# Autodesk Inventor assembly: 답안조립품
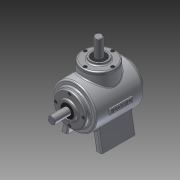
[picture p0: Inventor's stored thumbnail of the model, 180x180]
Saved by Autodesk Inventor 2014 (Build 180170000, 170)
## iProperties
Created: 2015-01
Part Number: 답안조립품
Document SubType Name: Assembly
Designer: user
Author: user
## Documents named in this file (15)
- C:\Users\user\Desktop\450106V1026\답안조립품.iam
- C:\Users\user\Desktop\450106V1026\1-본체.ipt
- C:\Users\user\Desktop\450106V1026\M4.ipt
- C:\Users\user\Desktop\450106V1026\메인 베벨기어.ipt
- C:\Users\user\Desktop\450106V1026\메인 축.ipt
- 메인 축.ipt
- C:\Users\user\Desktop\450106V1026\베어링 6203.ipt
- C:\Users\user\Desktop\450106V1026\서브 베벨기어.ipt
- C:\Users\user\Desktop\450106V1026\서브 축.ipt
- 서브 축.ipt
- C:\Users\user\Desktop\450106V1026\오일실.ipt
- C:\Users\user\Desktop\450106V1026\커버.ipt
- C:\Users\user\Desktop\450106V1026\커버2.ipt
- C:\Users\user\Desktop\450106V1026\키 4x4.ipt
- C:\Users\user\Desktop\450106V1026\키 5x5.ipt
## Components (13 placed, 2 different names)
1. 1-본체:1 — Insert:1, Insert:2, Insert:3, Insert:4, Insert:11, Insert:12
2. M4:9
3. M4:10
4. M4:11
5. M4:12
6. M4:2 — Insert:18
7. M4:3
8. M4:4
9. M4:5
10. M4:1 — Insert:19
11. M4:6
12. M4:7
13. M4:8
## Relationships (8: Insert 8)
- Insert:1: 1-본체:1
- Insert:2: 1-본체:1
- Insert:3: 1-본체:1
- Insert:4: 1-본체:1
- Insert:11: 1-본체:1
- Insert:12: 1-본체:1
- Insert:18: M4:2
- Insert:19: M4:1
## Named parameters: d8_d5 = 0, d9_d6 = 0
